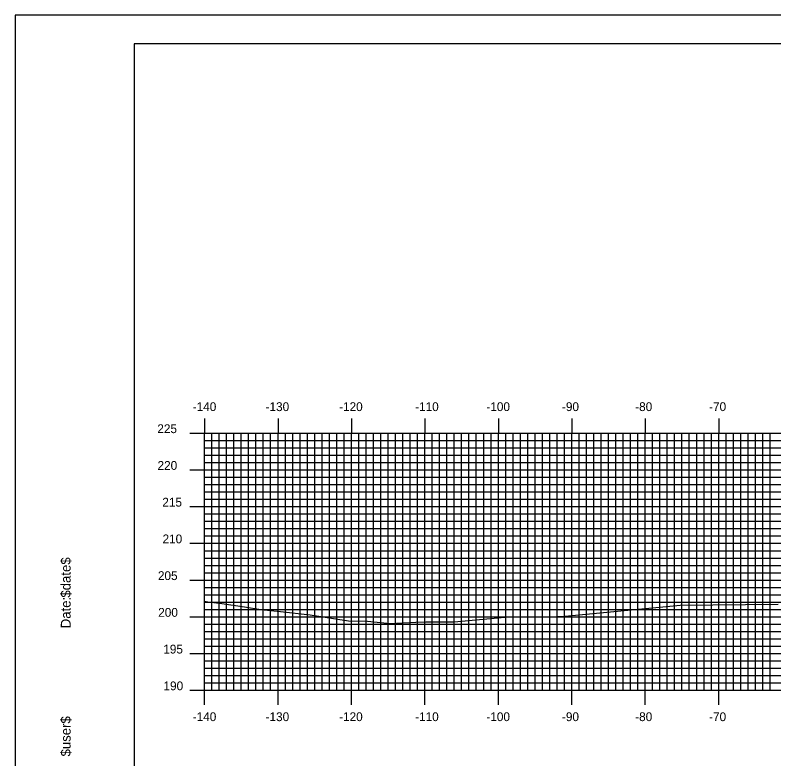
# Model space of a CAD drawing. Extents: x 852922 to 853266, y 364785 to 365005.
# Drawn here: x 852922.5 to 853025.7, y 364903.9 to 365005.1 of the extents above; entities that cross this region are included whole.
import ezdxf

# ---------------------------------------------------------------- set-up
doc = ezdxf.new("R2010")
doc.units = 0
for name, color, linetype in [('BORDER', 7, 'Continuous'), ('H_V ANNOTATION', 7, 'Continuous'), ('MAJOR', 7, 'Continuous'), ('MINOR', 7, 'Continuous'), ('PLOT BOUNDARY', 7, 'Continuous'), ('S_Roadway_Centerline', 7, 'Continuous')]:
    doc.layers.add(name, color=color, linetype=linetype)

msp = doc.modelspace()

# ---------------------------------------------------------------- linework, layer by layer
at = {"layer": 'BORDER'}
msp.add_lwpolyline([(852938.64, 364791.23), (853258.64, 364791.23), (853258.64, 365001.23), (852938.64, 365001.23)], close=True, dxfattribs=at)
at = {"layer": 'MAJOR'}
for p, q in [((852948.24, 364950.24), (852948.24, 364948.23)), ((852958.24, 364950.24), (852958.24, 364948.23)), ((852968.24, 364950.24), (852968.24, 364948.23)), ((852978.24, 364950.24), (852978.24, 364948.23)), ((852988.24, 364950.24), (852988.24, 364948.23)), ((852998.24, 364950.24), (852998.24, 364948.23)), ((853008.24, 364950.24), (853008.24, 364948.23)), ((853018.24, 364950.24), (853018.24, 364948.23)), ((852946.24, 364948.23), (852948.24, 364948.23)), ((852948.24, 364948.23), (853228.24, 364948.23)), ((852948.24, 364913.23), (852948.24, 364948.23)), ((852948.24, 364913.23), (852948.24, 364948.23)), ((852948.24, 364948.23), (853228.24, 364948.23)), ((852958.24, 364913.23), (852958.24, 364948.23)), ((852968.24, 364913.23), (852968.24, 364948.23)), ((852978.24, 364913.23), (852978.24, 364948.23)), ((852988.24, 364913.23), (852988.24, 364948.23)), ((852998.24, 364913.23), (852998.24, 364948.23)), ((853008.24, 364913.23), (853008.24, 364948.23)), ((853018.24, 364913.23), (853018.24, 364948.23)), ((852946.24, 364943.23), (852948.24, 364943.23)), ((852948.24, 364943.23), (853228.24, 364943.23)), ((852946.24, 364938.23), (852948.24, 364938.23)), ((852948.24, 364938.23), (853228.24, 364938.23)), ((852946.24, 364933.23), (852948.24, 364933.23)), ((852948.24, 364933.23), (853228.24, 364933.23)), ((852946.24, 364928.23), (852948.24, 364928.23)), ((852948.24, 364928.23), (853228.24, 364928.23)), ((852946.24, 364923.23), (852948.24, 364923.23)), ((852948.24, 364923.23), (853228.24, 364923.23)), ((852946.24, 364918.23), (852948.24, 364918.23)), ((852948.24, 364918.23), (853228.24, 364918.23)), ((852946.24, 364913.23), (852948.24, 364913.23)), ((852948.24, 364913.23), (853228.24, 364913.23)), ((852948.24, 364913.23), (853228.24, 364913.23)), ((852948.24, 364911.23), (852948.24, 364913.23)), ((852958.24, 364911.23), (852958.24, 364913.23)), ((852968.24, 364911.23), (852968.24, 364913.23)), ((852978.24, 364911.23), (852978.24, 364913.23)), ((852988.24, 364911.23), (852988.24, 364913.23)), ((852998.24, 364911.23), (852998.24, 364913.23)), ((853008.24, 364911.23), (853008.24, 364913.23)), ((853018.24, 364911.23), (853018.24, 364913.23))]:
    msp.add_line(p, q, dxfattribs=at)
at = {"layer": 'MINOR'}
for p, q in [((852949.24, 364913.23), (852949.24, 364948.23)), ((852950.24, 364913.23), (852950.24, 364948.23)), ((852951.24, 364913.23), (852951.24, 364948.23)), ((852952.24, 364913.23), (852952.24, 364948.23)), ((852953.24, 364913.23), (852953.24, 364948.23)), ((852954.24, 364913.23), (852954.24, 364948.23)), ((852955.24, 364913.23), (852955.24, 364948.23)), ((852956.24, 364913.23), (852956.24, 364948.23)), ((852957.24, 364913.23), (852957.24, 364948.23)), ((852959.24, 364913.23), (852959.24, 364948.23)), ((852960.24, 364913.23), (852960.24, 364948.23)), ((852961.24, 364913.23), (852961.24, 364948.23)), ((852962.24, 364913.23), (852962.24, 364948.23)), ((852963.24, 364913.23), (852963.24, 364948.23)), ((852964.24, 364913.23), (852964.24, 364948.23)), ((852965.24, 364913.23), (852965.24, 364948.23)), ((852966.24, 364913.23), (852966.24, 364948.23)), ((852967.24, 364913.23), (852967.24, 364948.23)), ((852969.24, 364913.23), (852969.24, 364948.23)), ((852970.24, 364913.23), (852970.24, 364948.23)), ((852971.24, 364913.23), (852971.24, 364948.23)), ((852972.24, 364913.23), (852972.24, 364948.23)), ((852973.24, 364913.23), (852973.24, 364948.23)), ((852974.24, 364913.23), (852974.24, 364948.23)), ((852975.24, 364913.23), (852975.24, 364948.23)), ((852976.24, 364913.23), (852976.24, 364948.23)), ((852977.24, 364913.23), (852977.24, 364948.23)), ((852979.24, 364913.23), (852979.24, 364948.23)), ((852980.24, 364913.23), (852980.24, 364948.23)), ((852981.24, 364913.23), (852981.24, 364948.23)), ((852982.24, 364913.23), (852982.24, 364948.23)), ((852983.24, 364913.23), (852983.24, 364948.23)), ((852984.24, 364913.23), (852984.24, 364948.23)), ((852985.24, 364913.23), (852985.24, 364948.23)), ((852986.24, 364913.23), (852986.24, 364948.23)), ((852987.24, 364913.23), (852987.24, 364948.23)), ((852989.24, 364913.23), (852989.24, 364948.23)), ((852990.24, 364913.23), (852990.24, 364948.23)), ((852991.24, 364913.23), (852991.24, 364948.23)), ((852992.24, 364913.23), (852992.24, 364948.23)), ((852993.24, 364913.23), (852993.24, 364948.23)), ((852994.24, 364913.23), (852994.24, 364948.23)), ((852995.24, 364913.23), (852995.24, 364948.23)), ((852996.24, 364913.23), (852996.24, 364948.23)), ((852997.24, 364913.23), (852997.24, 364948.23)), ((852999.24, 364913.23), (852999.24, 364948.23)), ((853000.24, 364913.23), (853000.24, 364948.23)), ((853001.24, 364913.23), (853001.24, 364948.23)), ((853002.24, 364913.23), (853002.24, 364948.23)), ((853003.24, 364913.23), (853003.24, 364948.23)), ((853004.24, 364913.23), (853004.24, 364948.23)), ((853005.24, 364913.23), (853005.24, 364948.23)), ((853006.24, 364913.23), (853006.24, 364948.23)), ((853007.24, 364913.23), (853007.24, 364948.23)), ((853009.24, 364913.23), (853009.24, 364948.23)), ((853010.24, 364913.23), (853010.24, 364948.23)), ((853011.24, 364913.23), (853011.24, 364948.23)), ((853012.24, 364913.23), (853012.24, 364948.23)), ((853013.24, 364913.23), (853013.24, 364948.23)), ((853014.24, 364913.23), (853014.24, 364948.23)), ((853015.24, 364913.23), (853015.24, 364948.23)), ((853016.24, 364913.23), (853016.24, 364948.23)), ((853017.24, 364913.23), (853017.24, 364948.23)), ((853019.24, 364913.23), (853019.24, 364948.23)), ((853020.24, 364913.23), (853020.24, 364948.23)), ((853021.24, 364913.23), (853021.24, 364948.23)), ((853022.24, 364913.23), (853022.24, 364948.23)), ((853023.24, 364913.23), (853023.24, 364948.23)), ((853024.24, 364913.23), (853024.24, 364948.23)), ((853025.24, 364913.23), (853025.24, 364948.23)), ((852948.24, 364947.23), (853228.24, 364947.23)), ((852948.24, 364947.23), (852950.25, 364947.23)), ((852948.24, 364946.23), (853228.24, 364946.23)), ((852948.24, 364946.23), (852950.25, 364946.23)), ((852948.24, 364945.23), (853228.24, 364945.23)), ((852948.24, 364945.23), (852950.25, 364945.23)), ((852948.24, 364944.23), (853228.24, 364944.23)), ((852948.24, 364944.23), (852950.25, 364944.23)), ((852948.24, 364942.23), (853228.24, 364942.23)), ((852948.24, 364942.23), (852950.25, 364942.23)), ((852948.24, 364941.23), (853228.24, 364941.23)), ((852948.24, 364941.23), (852950.25, 364941.23)), ((852948.24, 364940.23), (853228.24, 364940.23)), ((852948.24, 364940.23), (852950.25, 364940.23)), ((852948.24, 364939.23), (853228.24, 364939.23)), ((852948.24, 364939.23), (852950.25, 364939.23)), ((852948.24, 364937.23), (853228.24, 364937.23)), ((852948.24, 364937.23), (852950.25, 364937.23)), ((852948.24, 364936.23), (853228.24, 364936.23)), ((852948.24, 364936.23), (852950.25, 364936.23)), ((852948.24, 364935.23), (853228.24, 364935.23)), ((852948.24, 364935.23), (852950.25, 364935.23)), ((852948.24, 364934.23), (853228.24, 364934.23)), ((852948.24, 364934.23), (852950.25, 364934.23)), ((852948.24, 364932.23), (853228.24, 364932.23)), ((852948.24, 364932.23), (852950.25, 364932.23)), ((852948.24, 364931.23), (853228.24, 364931.23)), ((852948.24, 364931.23), (852950.25, 364931.23)), ((852948.24, 364930.23), (853228.24, 364930.23)), ((852948.24, 364930.23), (852950.25, 364930.23)), ((852948.24, 364929.23), (853228.24, 364929.23)), ((852948.24, 364929.23), (852950.25, 364929.23)), ((852948.24, 364927.23), (853228.24, 364927.23)), ((852948.24, 364927.23), (852950.25, 364927.23)), ((852948.24, 364926.23), (853228.24, 364926.23)), ((852948.24, 364926.23), (852950.25, 364926.23)), ((852948.24, 364925.23), (853228.24, 364925.23)), ((852948.24, 364925.23), (852950.25, 364925.23)), ((852948.24, 364924.23), (853228.24, 364924.23)), ((852948.24, 364924.23), (852950.25, 364924.23)), ((852948.24, 364922.23), (853228.24, 364922.23)), ((852948.24, 364922.23), (852950.25, 364922.23)), ((852948.24, 364921.23), (853228.24, 364921.23)), ((852948.24, 364921.23), (852950.25, 364921.23)), ((852948.24, 364920.23), (853228.24, 364920.23)), ((852948.24, 364920.23), (852950.25, 364920.23)), ((852948.24, 364919.23), (853228.24, 364919.23)), ((852948.24, 364919.23), (852950.25, 364919.23)), ((852948.24, 364917.23), (853228.24, 364917.23)), ((852948.24, 364917.23), (852950.25, 364917.23)), ((852948.24, 364916.23), (853228.24, 364916.23)), ((852948.24, 364916.23), (852950.25, 364916.23)), ((852948.24, 364915.23), (853228.24, 364915.23)), ((852948.24, 364915.23), (852950.25, 364915.23)), ((852948.24, 364914.23), (853228.24, 364914.23)), ((852948.24, 364914.23), (852950.25, 364914.23))]:
    msp.add_line(p, q, dxfattribs=at)
at = {"layer": 'PLOT BOUNDARY'}
msp.add_lwpolyline([(852922.46, 364785.11), (853262.46, 364785.11), (853262.46, 365005.11), (852922.46, 365005.11)], close=True, dxfattribs=at)
at = {"layer": 'S_Roadway_Centerline'}
msp.add_lwpolyline([(852948.24, 364925.34), (852948.67, 364925.28), (852950.26, 364925.07), (852953.69, 364924.59), (852955.89, 364924.24), (852958.58, 364923.96), (852962.61, 364923.49), (852967.85, 364922.67), (852970.42, 364922.64), (852973.51, 364922.33), (852977.01, 364922.51), (852978.35, 364922.55), (852982.24, 364922.55), (852989.64, 364923.21), (852996.3, 364923.27), (852996.84, 364923.29), (853012.97, 364924.81), (853026.35, 364924.97)], dxfattribs=at)

# ---------------------------------------------------------------- texts
at = {"layer": 'BORDER'}
for s, p in [('$date$', (852930.01, 364925.84)), ('Date:', (852930.01, 364921.67)), ('$user$', (852930.01, 364904.22))]:
    msp.add_text(s, height=1.339, rotation=90, dxfattribs=at).set_placement(p)
at = {"layer": 'H_V ANNOTATION'}
for s, p in [('-140', (852946.63, 364951.23)), ('-130', (852956.55, 364951.23)), ('-120', (852966.56, 364951.23)), ('-110', (852976.91, 364951.23)), ('-100', (852986.61, 364951.23)), ('-90', (852996.9, 364951.23)), ('-80', (853006.87, 364951.23)), ('-70', (853016.93, 364951.23)), ('225', (852941.81, 364948.23)), ('220', (852941.84, 364943.23)), ('215', (852942.49, 364938.23)), ('210', (852942.52, 364933.23)), ('205', (852941.89, 364928.23)), ('200', (852941.93, 364923.23)), ('195', (852942.62, 364918.23)), ('190', (852942.65, 364913.23)), ('-140', (852946.63, 364909.03)), ('-130', (852956.55, 364909.03)), ('-120', (852966.56, 364909.03)), ('-110', (852976.91, 364909.03)), ('-100', (852986.61, 364909.03)), ('-90', (852996.9, 364909.03)), ('-80', (853006.87, 364909.03)), ('-70', (853016.93, 364909.03))]:
    msp.add_text(s, height=1.2, dxfattribs=at).set_placement(p)
at = {"layer": 'MAJOR'}
msp.add_text('-', height=0.012, dxfattribs=at).set_placement((852948.23, 364913.23))

doc.saveas('drawing.dxf')
